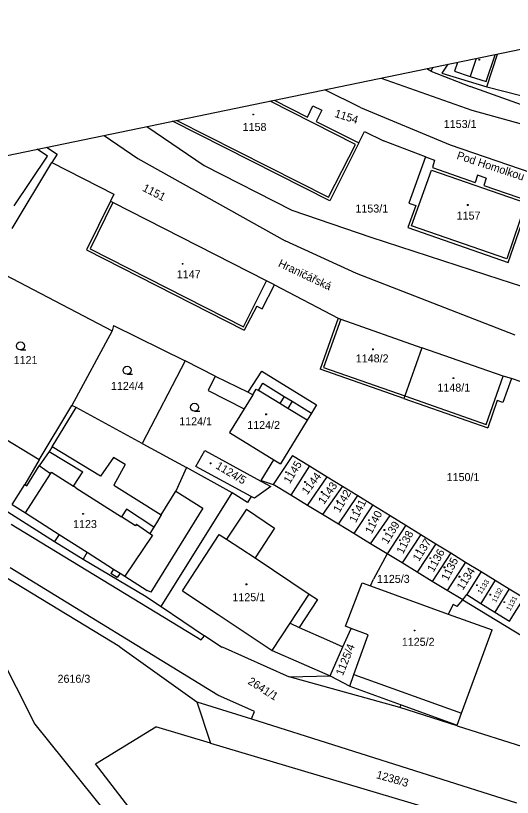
# Model space of a CAD drawing. Extents: x -804166 to -803706, y -1151030 to -1150147.
# Drawn here: x -804000.6 to -803907.6, y -1150293.8 to -1150147.3 of the extents above; entities that cross this region are included whole.
import ezdxf

# ---------------------------------------------------------------- set-up
doc = ezdxf.new("R2010")
doc.units = 0
for name, color, linetype in [('Default', 7, 'Continuous'), ('formát', 7, 'Continuous'), ('kn_celek - Cisla pozemkovych parcel', 7, 'Continuous'), ('kn_celek - Cisla stavebnich parcel', 7, 'Continuous'), ('kn_celek - Dalsi prvky mapy popis', 7, 'Continuous'), ('kn_celek - Hranice parcel', 7, 'Continuous'), ('kn_celek - Vnitrni kresby', 7, 'Continuous'), ('kn_celek - Znacky budov', 7, 'Continuous'), ('kn_celek - Znacky kultur', 7, 'Continuous')]:
    doc.layers.add(name, color=color, linetype=linetype)

# ---------------------------------------------------------------- blocks, each defined once
blk = doc.blocks.new('304')
at = {"layer": 'Default'}
blk.add_line((-0.1, 0), (9.9, 0), dxfattribs=at)
blk.add_circle((-0.1, 7.5), 7.5, dxfattribs=at)
blk = doc.blocks.new('402')
at = {"layer": 'Default'}
for p, q in [((-0.8, 0.8), (0.7, 0.8)), ((-0.8, 0.8), (-0.8, -0.7)), ((0.7, 0.8), (0.7, -0.7)), ((0.7, -0.7), (-0.8, -0.7))]:
    blk.add_line(p, q, dxfattribs=at)

msp = doc.modelspace()

# ---------------------------------------------------------------- linework, layer by layer
at = {"layer": 'formát'}
msp.add_line((-804166.3, -1150207.4), (-803875.43, -1150147.35), dxfattribs=at)
at = {"layer": 'kn_celek - Hranice parcel'}
for p, q in [((-803914.36, -1150155.38), (-803915.46, -1150158.73)), ((-803912.51, -1150159.68), (-803910.83, -1150154.66)), ((-803912.36, -1150160.67), (-803910.38, -1150154.56)), ((-803919.64, -1150156.47), (-803920.79, -1150158.15)), ((-803917.88, -1150156.11), (-803918.42, -1150157.77)), ((-803922.88, -1150157.75), (-803923.61, -1150157.3)), ((-803922.45, -1150157.05), (-803922.88, -1150157.75)), ((-803922.88, -1150157.75), (-803915.47, -1150160.65)), ((-803920.79, -1150158.15), (-803912.36, -1150160.67)), ((-803918.42, -1150157.77), (-803915.46, -1150158.73)), ((-803932.16, -1150159.06), (-803915.16, -1150165.04)), ((-803915.46, -1150158.73), (-803912.51, -1150159.68)), ((-803936.01, -1150164.57), (-803942.73, -1150161.24)), ((-803899.99, -1150166.2), (-803915.47, -1150160.65)), ((-803912.36, -1150160.67), (-803906, -1150162.31)), ((-803952.17, -1150163.19), (-803945.96, -1150166.34)), ((-803945.96, -1150166.34), (-803944.94, -1150164.25)), ((-803944.94, -1150164.25), (-803943.27, -1150165.07)), ((-803943.27, -1150165.07), (-803944.33, -1150167.17)), ((-803936.01, -1150164.57), (-803919.23, -1150171.55)), ((-803915.16, -1150165.04), (-803901.06, -1150168.96)), ((-803941.79, -1150182.02), (-803971.25, -1150167.13)), ((-803944.33, -1150167.17), (-803936.31, -1150171.17)), ((-803976.03, -1150168.12), (-803965.28, -1150175.44)), ((-803984.04, -1150169.77), (-803977.76, -1150174.09)), ((-803936.31, -1150171.17), (-803935.25, -1150169.08)), ((-803935.25, -1150169.08), (-803931.75, -1150170.83)), ((-803936.31, -1150171.17), (-803941.79, -1150182.02)), ((-803923.86, -1150173.81), (-803931.75, -1150170.83)), ((-803919.23, -1150171.55), (-803902.24, -1150177.36)), ((-803994.65, -1150173.69), (-803996.6, -1150172.36)), ((-803994.82, -1150172), (-803992.84, -1150173.31)), ((-804000.88, -1150182.97), (-803994.65, -1150173.69)), ((-803992.84, -1150173.31), (-803993.82, -1150174.86)), ((-803977.76, -1150174.09), (-803950.13, -1150189.56)), ((-803923.86, -1150173.81), (-803926.95, -1150182.49)), ((-803923.86, -1150173.81), (-803922.14, -1150174.41)), ((-803922.14, -1150174.41), (-803922.55, -1150175.8)), ((-804001.24, -1150187.2), (-803993.82, -1150174.86)), ((-803993.82, -1150174.86), (-803982.2, -1150180.79)), ((-803965.28, -1150175.44), (-803948.87, -1150183.77)), ((-803922.55, -1150175.8), (-803914.57, -1150178.58)), ((-803914.09, -1150177.21), (-803914.57, -1150178.58)), ((-803912.46, -1150177.78), (-803914.09, -1150177.21)), ((-803912.46, -1150177.78), (-803912.9, -1150179.16)), ((-803912.9, -1150179.16), (-803904.38, -1150182.12)), ((-803982.2, -1150180.79), (-803982.84, -1150182.1)), ((-803982.84, -1150182.1), (-803987.32, -1150191.24)), ((-803982.39, -1150182.32), (-803982.84, -1150182.1)), ((-803953.64, -1150197.02), (-803982.39, -1150182.32)), ((-803925.66, -1150182.93), (-803927.15, -1150187.06)), ((-803926.95, -1150182.49), (-803925.66, -1150182.93)), ((-803908.4, -1150193.58), (-803904.38, -1150182.12)), ((-803948.87, -1150183.77), (-803934.09, -1150188.82)), ((-803927.15, -1150187.06), (-803908.4, -1150193.58)), ((-803934.09, -1150188.82), (-803909.95, -1150196.71)), ((-803936.79, -1150195.65), (-803950.13, -1150189.56)), ((-803987.32, -1150191.24), (-803957.79, -1150206.26)), ((-804005.52, -1150194.37), (-803982.57, -1150206.4)), ((-803907.04, -1150207.19), (-803936.79, -1150195.65)), ((-803954.42, -1150202.26), (-803952.16, -1150197.77)), ((-803952.16, -1150197.77), (-803953.64, -1150197.02)), ((-803952.16, -1150197.77), (-803940.18, -1150204.04)), ((-803909.95, -1150196.71), (-803888.51, -1150203.65)), ((-803955.45, -1150201.77), (-803957.79, -1150206.26)), ((-803955.45, -1150201.77), (-803954.42, -1150202.26)), ((-803940.18, -1150204.04), (-803943.58, -1150213.54)), ((-803940.18, -1150204.04), (-803939.7, -1150204.21)), ((-803939.7, -1150204.21), (-803924.55, -1150209.58)), ((-803982.57, -1150206.4), (-803990.09, -1150220.35)), ((-803982.3, -1150205.37), (-803982.57, -1150206.4)), ((-803982.3, -1150205.37), (-803968.85, -1150212.02)), ((-803924.55, -1150209.58), (-803927.71, -1150218.58)), ((-803909.31, -1150214.86), (-803924.55, -1150209.58)), ((-803968.85, -1150212.02), (-803976.92, -1150227.5)), ((-803963.22, -1150214.91), (-803968.85, -1150212.02)), ((-803957.07, -1150217.85), (-803954.52, -1150213.96)), ((-803954.52, -1150213.96), (-803944.24, -1150220.27)), ((-803927.88, -1150219.05), (-803943.58, -1150213.54)), ((-803963.22, -1150214.91), (-803964.57, -1150217.57)), ((-803963.22, -1150214.91), (-803957.07, -1150217.85)), ((-803907.76, -1150215.33), (-803909.34, -1150219.79)), ((-803907.76, -1150215.33), (-803909.31, -1150214.86)), ((-803895.6, -1150219.58), (-803907.76, -1150215.33)), ((-803964.57, -1150217.57), (-803957.8, -1150220.97)), ((-803927.71, -1150218.58), (-803927.88, -1150219.05)), ((-803927.88, -1150219.05), (-803912.19, -1150224.55)), ((-803910.4, -1150219.46), (-803912.19, -1150224.55)), ((-803909.34, -1150219.79), (-803910.4, -1150219.46)), ((-803996.21, -1150230.54), (-804012.29, -1150220.87)), ((-803996.21, -1150230.54), (-803990.09, -1150220.35)), ((-803989.3, -1150220.78), (-803990.09, -1150220.35)), ((-803976.92, -1150227.5), (-803989.3, -1150220.78)), ((-803957.8, -1150220.97), (-803960.56, -1150225.44)), ((-803944.24, -1150220.27), (-803945.18, -1150221.8)), ((-803945.18, -1150221.8), (-803945.99, -1150223.14)), ((-803945.99, -1150223.14), (-803951.03, -1150231.31)), ((-803960.56, -1150225.44), (-803952.26, -1150230.55)), ((-803976.92, -1150227.5), (-803976.82, -1150227.54)), ((-803976.82, -1150227.54), (-803968.61, -1150232.01)), ((-803966.85, -1150231.81), (-803965.2, -1150228.83)), ((-803965.2, -1150228.83), (-803954.67, -1150234.53)), ((-803948.76, -1150229.77), (-803952.4, -1150235.17)), ((-803948.76, -1150229.77), (-803945.6, -1150231.68)), ((-803996.21, -1150230.54), (-803998.92, -1150235.16)), ((-803954.61, -1150234.43), (-803952.26, -1150230.55)), ((-803952.26, -1150230.55), (-803951.03, -1150231.31)), ((-803945.6, -1150231.68), (-803949.07, -1150237.2)), ((-803945.6, -1150231.68), (-803942.29, -1150233.72)), ((-803960.05, -1150236.75), (-803968.61, -1150232.01)), ((-803956.49, -1150237.42), (-803966.85, -1150231.81)), ((-803954.67, -1150234.53), (-803954.61, -1150234.43)), ((-803954.67, -1150234.53), (-803952.83, -1150235.52)), ((-803954.61, -1150234.43), (-803952.4, -1150235.17)), ((-803945.96, -1150239.09), (-803942.29, -1150233.72)), ((-803942.29, -1150233.72), (-803939.41, -1150235.49)), ((-804001.25, -1150238.93), (-803998.92, -1150235.16)), ((-803952.83, -1150235.52), (-803955.9, -1150237.73)), ((-803949.07, -1150237.2), (-803952.4, -1150235.17)), ((-803939.41, -1150235.49), (-803943.15, -1150240.8)), ((-803939.41, -1150235.49), (-803936.54, -1150237.26)), ((-803973.34, -1150258.03), (-803960.05, -1150236.75)), ((-803957.19, -1150238.54), (-803960.05, -1150236.75)), ((-803956.49, -1150237.42), (-803957.19, -1150238.54)), ((-803955.9, -1150237.73), (-803956.49, -1150237.42)), ((-803945.96, -1150239.09), (-803949.07, -1150237.2)), ((-803940.16, -1150242.62), (-803936.54, -1150237.26)), ((-803936.54, -1150237.26), (-803933.72, -1150238.99)), ((-803933.72, -1150238.99), (-803937.3, -1150244.36)), ((-803933.72, -1150238.99), (-803930.49, -1150240.98)), ((-804002.08, -1150240.27), (-803993.33, -1150245.84)), ((-803943.15, -1150240.8), (-803945.96, -1150239.09)), ((-803940.16, -1150242.62), (-803943.15, -1150240.8)), ((-803934.18, -1150246.26), (-803930.49, -1150240.98)), ((-803930.49, -1150240.98), (-803927.51, -1150242.81)), ((-804001.47, -1150242.58), (-803965.84, -1150264.29)), ((-803937.3, -1150244.36), (-803940.16, -1150242.62)), ((-803927.51, -1150242.81), (-803931.06, -1150248.16)), ((-803927.51, -1150242.81), (-803924.75, -1150244.51)), ((-803934.18, -1150246.26), (-803937.3, -1150244.36)), ((-803924.75, -1150244.51), (-803928.25, -1150249.87)), ((-803924.75, -1150244.51), (-803921.91, -1150246.26)), ((-803993.33, -1150245.84), (-803987.97, -1150249.18)), ((-803931.06, -1150248.16), (-803934.18, -1150246.26)), ((-803921.91, -1150246.26), (-803925.44, -1150251.58)), ((-803921.91, -1150246.26), (-803919.1, -1150247.99)), ((-803987.97, -1150249.18), (-803976.51, -1150255.94)), ((-803931.06, -1150248.16), (-803933.58, -1150252.91)), ((-803928.25, -1150249.87), (-803931.06, -1150248.16)), ((-803919.1, -1150247.99), (-803922.58, -1150253.32)), ((-803919.1, -1150247.99), (-803916.33, -1150249.69)), ((-803925.44, -1150251.58), (-803928.25, -1150249.87)), ((-803916.33, -1150249.69), (-803919.8, -1150255.01)), ((-803916.33, -1150249.69), (-803913.44, -1150251.47)), ((-803981.13, -1150265.6), (-804004.96, -1150251.13)), ((-803962.74, -1150274.61), (-804001.67, -1150250.78)), ((-803922.58, -1150253.32), (-803925.44, -1150251.58)), ((-803913.44, -1150251.47), (-803916.09, -1150255.76)), ((-803913.44, -1150251.47), (-803910.81, -1150253.09)), ((-803938.84, -1150261.73), (-803935.72, -1150253.58)), ((-803935.72, -1150253.58), (-803934.14, -1150254.15)), ((-803934.14, -1150254.15), (-803933.58, -1150252.91)), ((-803919.8, -1150255.01), (-803922.58, -1150253.32)), ((-803910.81, -1150253.09), (-803913.49, -1150257.44)), ((-803910.81, -1150253.09), (-803908.17, -1150254.71)), ((-803934.14, -1150254.15), (-803919.6, -1150259.43)), ((-803916.86, -1150256.8), (-803919.8, -1150255.01)), ((-803908.17, -1150254.71), (-803910.85, -1150259.06)), ((-803908.17, -1150254.71), (-803905.37, -1150256.41)), ((-804009.55, -1150255.32), (-803997.02, -1150280.06)), ((-803976.51, -1150255.94), (-803973.34, -1150258.03)), ((-803916.86, -1150256.8), (-803916.09, -1150255.76)), ((-803916.09, -1150255.76), (-803913.49, -1150257.44)), ((-803908.13, -1150260.76), (-803905.37, -1150256.41)), ((-803973.34, -1150258.03), (-803965.24, -1150263.54)), ((-803918.68, -1150257.65), (-803919.6, -1150259.43)), ((-803917.94, -1150258.03), (-803918.68, -1150257.65)), ((-803917.94, -1150258.03), (-803916.86, -1150256.8)), ((-803916.86, -1150256.8), (-803895.91, -1150269.48)), ((-803913.49, -1150257.44), (-803910.85, -1150259.06)), ((-803919.6, -1150259.43), (-803911.36, -1150262.42)), ((-803910.85, -1150259.06), (-803908.13, -1150260.76)), ((-803939.31, -1150265.6), (-803937.75, -1150262.15)), ((-803937.75, -1150262.15), (-803938.84, -1150261.73)), ((-803934.57, -1150263.36), (-803937.75, -1150262.15)), ((-803917.08, -1150278.02), (-803911.36, -1150262.42)), ((-803965.84, -1150264.29), (-803965.24, -1150263.54)), ((-803962.03, -1150265.73), (-803965.24, -1150263.54)), ((-803937.25, -1150270.73), (-803934.57, -1150263.36)), ((-803981.13, -1150265.6), (-803966.71, -1150275.85)), ((-803961.93, -1150265.57), (-803962.03, -1150265.73)), ((-803961.93, -1150265.57), (-803949.39, -1150271.17)), ((-803941.73, -1150270.98), (-803939.31, -1150265.6)), ((-803949.39, -1150271.17), (-803941.73, -1150270.98)), ((-803928.65, -1150276.96), (-803949.39, -1150271.17)), ((-803938.05, -1150272.93), (-803937.25, -1150270.73)), ((-803938.05, -1150272.93), (-803928.38, -1150276.45)), ((-803955.88, -1150277.72), (-803962.74, -1150274.61)), ((-803966.71, -1150275.85), (-803956.46, -1150279.09)), ((-803966.71, -1150275.85), (-803964.13, -1150283.6)), ((-803928.65, -1150276.96), (-803928.38, -1150276.45)), ((-803917.94, -1150280.35), (-803928.65, -1150276.96)), ((-803928.38, -1150276.45), (-803917.91, -1150280.27)), ((-803956.46, -1150279.09), (-803955.88, -1150277.72)), ((-803917.91, -1150280.27), (-803917.08, -1150278.02)), ((-803956.46, -1150279.09), (-803906.79, -1150294.77)), ((-803997.02, -1150280.06), (-803982.8, -1150297.76)), ((-803985.68, -1150287.47), (-803974.38, -1150280.55)), ((-803964.13, -1150283.6), (-803974.38, -1150280.55)), ((-803917.94, -1150280.35), (-803904.51, -1150284.6)), ((-803964.13, -1150283.6), (-803909.59, -1150299.84)), ((-803936.41, -1150351.52), (-803985.68, -1150287.47))]:
    msp.add_line(p, q, dxfattribs=at)
at = {"layer": 'kn_celek - Vnitrni kresby'}
for p, q in [((-803936.99, -1150171.46), (-803952.95, -1150163.35)), ((-803970.42, -1150166.96), (-803941.99, -1150181.36)), ((-803941.99, -1150181.36), (-803936.99, -1150171.46)), ((-803926.46, -1150186.72), (-803922.71, -1150176.27)), ((-803922.71, -1150176.27), (-803905.04, -1150182.42)), ((-803982.39, -1150182.32), (-803986.68, -1150191.06)), ((-803905.04, -1150182.42), (-803908.64, -1150192.92)), ((-803908.64, -1150192.92), (-803926.46, -1150186.72)), ((-803986.68, -1150191.06), (-803957.93, -1150205.62)), ((-803955.9, -1150201.54), (-803953.64, -1150197.02)), ((-803957.93, -1150205.62), (-803955.9, -1150201.54)), ((-803939.7, -1150204.21), (-803942.94, -1150213.23)), ((-803942.94, -1150213.23), (-803927.71, -1150218.58)), ((-803910.86, -1150219.32), (-803909.31, -1150214.86)), ((-803955.12, -1150217.54), (-803954.3, -1150216.2)), ((-803954.3, -1150216.2), (-803950.3, -1150218.66)), ((-803956.21, -1150218.38), (-803957.8, -1150220.97)), ((-803957.07, -1150217.85), (-803956.21, -1150218.38)), ((-803956.21, -1150218.38), (-803955.55, -1150217.32)), ((-803955.55, -1150217.32), (-803955.12, -1150217.54)), ((-803951.13, -1150220), (-803955.12, -1150217.54)), ((-803950.3, -1150218.66), (-803951.13, -1150220)), ((-803950.3, -1150218.66), (-803948.82, -1150219.57)), ((-803948.82, -1150219.57), (-803949.65, -1150220.91)), ((-803948.82, -1150219.57), (-803945.18, -1150221.8)), ((-803927.71, -1150218.58), (-803912.51, -1150223.91)), ((-803912.51, -1150223.91), (-803910.86, -1150219.32)), ((-803993.76, -1150228.13), (-803989.3, -1150220.78)), ((-803949.65, -1150220.91), (-803951.13, -1150220)), ((-803945.99, -1150223.14), (-803949.65, -1150220.91)), ((-803993.76, -1150228.13), (-803994.35, -1150229)), ((-803984.7, -1150233.64), (-803993.76, -1150228.13)), ((-803994.35, -1150229), (-803996.19, -1150231.69)), ((-803994.35, -1150229), (-803988.06, -1150232.8)), ((-803982.28, -1150230.11), (-803984.7, -1150233.64)), ((-803980.09, -1150231.42), (-803982.28, -1150230.11)), ((-803980.09, -1150231.42), (-803982.21, -1150235.3)), ((-803998.5, -1150235.42), (-803996.19, -1150231.69)), ((-803994.12, -1150233.18), (-803996.19, -1150231.69)), ((-803994.12, -1150233.18), (-803993.91, -1150232.85)), ((-803993.91, -1150232.85), (-803989.78, -1150235.5)), ((-803989.78, -1150235.5), (-803988.06, -1150232.8)), ((-803968.61, -1150232.01), (-803970.59, -1150236.41)), ((-803998.77, -1150240.51), (-803994.12, -1150233.18)), ((-803998.92, -1150235.16), (-803998.5, -1150235.42)), ((-803989.36, -1150235.77), (-803989.78, -1150235.5)), ((-803989.36, -1150235.77), (-803980.82, -1150241.24)), ((-803982.21, -1150235.3), (-803973.34, -1150240.88)), ((-803973.34, -1150240.88), (-803970.59, -1150236.41)), ((-803970.59, -1150236.41), (-803965.56, -1150239.61)), ((-804001.25, -1150238.93), (-803998.77, -1150240.51)), ((-803979.85, -1150239.79), (-803980.82, -1150241.24)), ((-803974.76, -1150243.18), (-803979.85, -1150239.79)), ((-803965.56, -1150239.61), (-803975.3, -1150255.36)), ((-803957.39, -1150239.78), (-803961.14, -1150245.41)), ((-803957.39, -1150239.78), (-803952.13, -1150243.37)), ((-803998.77, -1150240.51), (-803992.48, -1150244.51)), ((-803978.19, -1150242.94), (-803980.82, -1150241.24)), ((-803973.34, -1150240.88), (-803974.05, -1150242.03)), ((-803978.01, -1150242.62), (-803978.19, -1150242.94)), ((-803978.01, -1150242.62), (-803975.46, -1150244.34)), ((-803974.76, -1150243.18), (-803975.46, -1150244.34)), ((-803974.05, -1150242.03), (-803974.76, -1150243.18)), ((-803952.13, -1150243.37), (-803955.76, -1150248.9)), ((-803992.48, -1150244.51), (-803993.33, -1150245.84)), ((-803992.48, -1150244.51), (-803987.2, -1150247.87)), ((-803974.96, -1150244.64), (-803980.17, -1150252.33)), ((-803975.46, -1150244.34), (-803974.96, -1150244.64)), ((-803969.37, -1150255.07), (-803962.48, -1150244.54)), ((-803962.48, -1150244.54), (-803961.14, -1150245.41)), ((-803961.14, -1150245.41), (-803955.76, -1150248.9)), ((-803987.2, -1150247.87), (-803987.97, -1150249.18)), ((-803987.2, -1150247.87), (-803982.27, -1150251)), ((-803955.76, -1150248.9), (-803945.65, -1150255.69)), ((-803982.27, -1150251), (-803982.81, -1150251.84)), ((-803981.6, -1150252.61), (-803982.81, -1150251.84)), ((-803982.27, -1150251), (-803981.06, -1150251.77)), ((-803981.06, -1150251.77), (-803981.6, -1150252.61)), ((-803981.06, -1150251.77), (-803980.17, -1150252.33)), ((-803980.17, -1150252.33), (-803975.96, -1150255.01)), ((-803975.3, -1150255.36), (-803975.96, -1150255.01)), ((-803969.37, -1150255.07), (-803962.66, -1150259.54)), ((-803949.23, -1150261.17), (-803945.65, -1150255.69)), ((-803945.65, -1150255.69), (-803944.11, -1150256.73)), ((-803944.11, -1150256.73), (-803947.51, -1150261.94)), ((-803962.66, -1150259.54), (-803952.55, -1150266.27)), ((-803952.55, -1150266.27), (-803949.23, -1150261.17)), ((-803949.23, -1150261.17), (-803947.51, -1150261.94)), ((-803947.51, -1150261.94), (-803941.84, -1150264.47)), ((-803941.84, -1150264.47), (-803939.31, -1150265.6)), ((-803952.55, -1150266.27), (-803941.73, -1150270.98)), ((-803941.73, -1150270.98), (-803938.05, -1150272.93)), ((-803937.25, -1150270.73), (-803917.08, -1150278.02))]:
    msp.add_line(p, q, dxfattribs=at)

# ---------------------------------------------------------------- block references
at = {"layer": 'kn_celek - Znacky budov', "xscale": 0.1, "yscale": 0.10000000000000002}
for p in [(-803913.79, -1150155.61), (-803956.13, -1150165.89), (-803915.96, -1150182.83), (-803969.36, -1150193.85), (-803933.7, -1150209.86), (-803918.63, -1150215.27), (-803953.73, -1150222.03), (-803964.13, -1150231.2), (-803949.98, -1150232.86), (-803946.42, -1150234.71), (-803943.3, -1150236.57), (-803940.4, -1150238.28), (-803937.5, -1150239.91), (-803987.99, -1150240.68), (-803934.46, -1150241.85), (-803931.56, -1150243.7), (-803928.66, -1150245.62), (-803925.61, -1150247.49), (-803922.99, -1150248.96), (-803920.31, -1150250.7), (-803917.52, -1150252.45), (-803957.4, -1150253.88), (-803914.25, -1150254.03), (-803911.72, -1150255.81), (-803909.12, -1150257.23), (-803925.9, -1150262.54)]:
    msp.add_blockref('402', p, dxfattribs=at)
at = {"layer": 'kn_celek - Znacky kultur', "xscale": 0.1, "yscale": 0.10000000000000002}
for p in [(-803999.7, -1150209.97), (-803979.73, -1150214.53), (-803967.1, -1150221.45)]:
    msp.add_blockref('304', p, dxfattribs=at)

# ---------------------------------------------------------------- texts
at = {"layer": 'kn_celek - Cisla pozemkovych parcel'}
for s, rotation, p in [('1154', 342, (-803940.99, -1150166.28)), ('1151', 333, (-803977, -1150180.1)), ('1125/4', 68.2006, (-803939.34, -1150271.1)), ('2641/1', 327.6, (-803957.26, -1150272.41)), ('1238/3', 343.8, (-803933.19, -1150290.15))]:
    msp.add_text(s, height=1.5, rotation=rotation, dxfattribs=at).set_placement(p)
for s, p in [('1153/1', (-803920.43, -1150168.39)), ('1153/1', (-803936.98, -1150184.23)), ('1121', (-804000.99, -1150212.61)), ('1124/4', (-803982.77, -1150217.46)), ('1124/1', (-803969.98, -1150224.09)), ('1150/1', (-803919.89, -1150234.53)), ('1125/3', (-803932.95, -1150253.6)), ('2616/3', (-803992.77, -1150272.31))]:
    msp.add_text(s, height=1.5, dxfattribs=at).set_placement(p)
at = {"layer": 'kn_celek - Cisla stavebnich parcel'}
for s, p in [('1158', (-803958.1, -1150168.95)), ('1157', (-803918.02, -1150185.55)), ('1147', (-803970.44, -1150196.54)), ('1148/2', (-803936.91, -1150212.3)), ('1148/1', (-803921.62, -1150217.77)), ('1124/2', (-803957.24, -1150224.78)), ('1123', (-803989.86, -1150243.33)), ('1125/1', (-803960.02, -1150257.03)), ('1125/2', (-803928.29, -1150265.39))]:
    msp.add_text(s, height=1.5, dxfattribs=at).set_placement(p)
for s, height, rotation, p in [('1124/5', 1.5, 329.2871, (-803963.28, -1150232.07)), ('1145', 1.5, 58.3925, (-803949.27, -1150235.15)), ('1144', 1.5, 52.5238, (-803946, -1150237.19)), ('1143', 1.5, 54.7276, (-803942.86, -1150239.01)), ('1142', 1.5, 59.7435, (-803939.96, -1150240.57)), ('1141', 1.5, 63.435, (-803936.89, -1150242.44)), ('1140', 1.5, 62.7447, (-803933.94, -1150244.54)), ('1139', 1.5, 57.9947, (-803930.97, -1150246.45)), ('1138', 1.5, 63.435, (-803928.05, -1150248.29)), ('1137', 1.5, 57.5288, (-803925.1, -1150249.7)), ('1136', 1.5, 60.9454, (-803922.35, -1150251.69)), ('1135', 1.5, 63.435, (-803919.66, -1150253.32)), ('1134', 1.5, 57.9947, (-803916.86, -1150255.09)), ('1133', 0.94, 57.5288, (-803913.4, -1150255.79)), ('1132', 0.94, 62.1027, (-803910.69, -1150257.37)), ('1131', 0.94, 62.1027, (-803907.97, -1150258.93))]:
    msp.add_text(s, height=height, rotation=rotation, dxfattribs=at).set_placement(p)
at = {"layer": 'kn_celek - Dalsi prvky mapy popis'}
for s, rotation, p in [('Pod Homolkou', 341.7816, (-803918.12, -1150174.15)), ('Hraničářská', 334.7307, (-803951.57, -1150194.27))]:
    msp.add_text(s, height=1.5, rotation=rotation, dxfattribs=at).set_placement(p)

doc.saveas('drawing.dxf')
